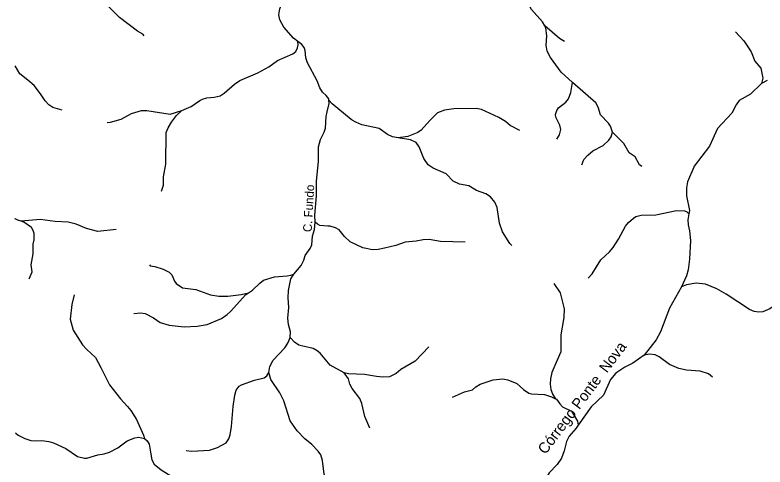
# Model space of a CAD drawing. Extents: x 473.9 to 500, y 7733.1 to 7760.8.
# Drawn here: x 473.92 to 480.86, y 7737.12 to 7741.31 of the extents above; entities that cross this region are included whole.
import ezdxf
from ezdxf.enums import TextEntityAlignment as Align

# ---------------------------------------------------------------- set-up
doc = ezdxf.new("R2010")
doc.units = 0
doc.header["$LTSCALE"] = 0.032
doc.layers.add('61', color=7, linetype='Continuous')
doc.layers.add('7', color=7, linetype='Continuous', lineweight=25)

msp = doc.modelspace()

# ---------------------------------------------------------------- linework, layer by layer
at = {"layer": '7'}
msp.add_line((480.8795, 7740.7), (480.8283, 7740.6712), dxfattribs=at)
for points in [[(476.5367, 7741.0622), (476.4959, 7741.093), (476.4064, 7741.1932), (476.3697, 7741.2629), (476.3611, 7741.3075), (476.3698, 7741.363), (476.4227, 7741.4977), (476.4668, 7741.6417), (476.4725, 7741.7305), (476.4574, 7741.8809), (476.4683, 7741.9924), (476.477, 7742.0153), (476.5332, 7742.0846), (476.7005, 7742.1941), (476.7489, 7742.2298), (476.7736, 7742.2599), (476.7997, 7742.3225), (476.7985, 7742.4024), (476.8151, 7742.4488), (476.8164, 7742.4524)], [(478.8237, 7741.2052), (478.8022, 7741.2433), (478.6995, 7741.3579), (478.6763, 7741.4023), (478.6692, 7741.427), (478.6711, 7741.5326), (478.639, 7741.658), (478.6382, 7741.6879), (478.6449, 7741.7268), (478.6824, 7741.8322), (478.6863, 7741.8993), (478.6996, 7741.9735), (478.7164, 7742.0043), (478.8564, 7742.1009), (478.9218, 7742.1576), (478.9456, 7742.1881)], [(475.1163, 7741.1132), (475.1013, 7741.1306), (475.0542, 7741.1583), (474.8855, 7741.2827), (474.793, 7741.3767), (474.6769, 7741.509), (474.6163, 7741.6049), (474.5903, 7741.6637), (474.578, 7741.7029), (474.5723, 7741.7783), (474.547, 7741.8325), (474.5162, 7741.882), (474.4613, 7741.9302), (474.4173, 7741.9689), (474.3764, 7742.0123), (474.3649, 7742.0365), (474.3658, 7742.0767), (474.3836, 7742.1527)], [(479.0794, 7740.6833), (478.9728, 7740.7761), (478.8759, 7740.9133), (478.8454, 7740.972), (478.8355, 7741.027), (478.8403, 7741.1121), (478.8308, 7741.1926), (478.8237, 7741.2052)], [(479.0038, 7741.0613), (478.9591, 7741.0894), (478.8237, 7741.2052)], [(480.5889, 7741.1508), (480.6655, 7741.0671), (480.7315, 7740.9659), (480.7673, 7740.8796), (480.8231, 7740.8132), (480.8414, 7740.7225), (480.8283, 7740.6712)], [(475.4648, 7740.4217), (475.5508, 7740.459), (475.6285, 7740.5147), (475.6555, 7740.5278), (475.6945, 7740.5398), (475.7625, 7740.5447), (475.8186, 7740.5585), (475.8565, 7740.5837), (475.9498, 7740.6673), (476.0009, 7740.7014), (476.1672, 7740.7712), (476.2676, 7740.8255), (476.3496, 7740.8857), (476.4921, 7740.9457), (476.5184, 7740.9699), (476.5345, 7741.0016), (476.5407, 7741.0314), (476.5367, 7741.0622)], [(476.8242, 7740.5167), (476.8231, 7740.5294), (476.7978, 7740.5626), (476.7639, 7740.5933), (476.7398, 7740.6315), (476.7145, 7740.6981), (476.6271, 7740.8632), (476.6105, 7740.9108), (476.6049, 7740.9778), (476.596, 7741.0073), (476.5743, 7741.0337), (476.5738, 7741.0343), (476.5367, 7741.0622)], [(474.356, 7740.4271), (474.2699, 7740.4506), (474.2331, 7740.4741), (474.1975, 7740.5118), (474.1551, 7740.5771), (474.0958, 7740.6532), (474.0395, 7740.7041), (473.9649, 7740.7616), (473.9194, 7740.8355)], [(478.9334, 7740.1578), (478.9575, 7740.1981), (478.9701, 7740.2462), (478.9627, 7740.286), (478.9242, 7740.362), (478.9228, 7740.3854), (478.9348, 7740.4234), (478.9506, 7740.4458), (479.0172, 7740.4995), (479.043, 7740.5319), (479.0623, 7740.5904), (479.0794, 7740.6833)], [(479.4502, 7740.2217), (479.4314, 7740.277), (479.4133, 7740.3056), (479.3366, 7740.3838), (479.3167, 7740.4534), (479.2956, 7740.4932), (479.0794, 7740.6833)], [(480.8283, 7740.6712), (480.7274, 7740.575), (480.6199, 7740.5164), (480.5921, 7740.4763), (480.5527, 7740.3963), (480.4199, 7740.255), (480.3463, 7740.0922), (480.2063, 7739.9073), (480.202, 7739.8973), (480.1446, 7739.7626), (480.1335, 7739.7078), (480.1351, 7739.6311), (480.1615, 7739.4974), (480.1565, 7739.4666)], [(476.6969, 7739.3887), (476.6939, 7739.4525), (476.7082, 7739.6311), (476.7099, 7739.7687), (476.7291, 7739.9515), (476.7276, 7740.0871), (476.7471, 7740.1553), (476.7804, 7740.2215), (476.7925, 7740.2603), (476.7997, 7740.3674), (476.8092, 7740.4093), (476.8269, 7740.4871), (476.8242, 7740.5167)], [(477.4664, 7740.168), (477.4128, 7740.1786), (477.3682, 7740.1988), (477.2895, 7740.256), (477.1293, 7740.2899), (477.0739, 7740.3137), (477.0394, 7740.3337), (477.032, 7740.338), (476.856, 7740.4832), (476.8242, 7740.5167)], [(474.7722, 7740.3117), (474.8045, 7740.314), (474.9021, 7740.3409), (474.9977, 7740.3939), (475.0887, 7740.4212), (475.14, 7740.4236), (475.3551, 7740.3891), (475.4648, 7740.4217)], [(475.2765, 7739.674), (475.293, 7739.7312), (475.2935, 7739.809), (475.3147, 7739.9249), (475.3184, 7740.2179), (475.3358, 7740.2605), (475.3673, 7740.3132), (475.413, 7740.375), (475.4648, 7740.4217)], [(478.5905, 7740.2379), (478.5028, 7740.283), (478.458, 7740.3203), (478.3982, 7740.358), (478.2365, 7740.4321), (478.1878, 7740.4413), (477.9812, 7740.4372), (477.8933, 7740.4252), (477.8308, 7740.3995), (477.7587, 7740.3314), (477.6798, 7740.2414), (477.6474, 7740.2185), (477.5536, 7740.1823), (477.4664, 7740.168)], [(479.165, 7739.9209), (479.184, 7739.9695), (479.2193, 7740.0083), (479.2681, 7740.0479), (479.3634, 7740.0974), (479.4165, 7740.1492), (479.4358, 7740.178), (479.4502, 7740.2217)], [(479.72, 7739.9041), (479.6989, 7739.9205), (479.6598, 7739.992), (479.604, 7740.0299), (479.555, 7740.1162), (479.4502, 7740.2217)], [(478.519, 7739.1731), (478.4978, 7739.1903), (478.4315, 7739.2993), (478.4048, 7739.3785), (478.3829, 7739.5251), (478.3595, 7739.5731), (478.3212, 7739.622), (478.2768, 7739.6505), (478.1913, 7739.6824), (478.1181, 7739.7251), (478.0333, 7739.7393), (477.9746, 7739.7667), (477.9101, 7739.8351), (477.7909, 7739.8887), (477.7444, 7739.9207), (477.7038, 7739.9768), (477.66, 7740.0868), (477.6314, 7740.1265), (477.5784, 7740.1512), (477.4664, 7740.168)], [(479.2247, 7738.8694), (479.2612, 7738.9101), (479.3408, 7739.0394), (479.42, 7739.1128), (479.4557, 7739.1538), (479.5051, 7739.2311), (479.5691, 7739.3524), (479.5958, 7739.3864), (479.6421, 7739.4268), (479.6642, 7739.4394), (479.7133, 7739.4542), (479.8502, 7739.4551), (480.042, 7739.4967), (480.1152, 7739.4945), (480.135, 7739.4863), (480.1565, 7739.4666)], [(473.9779, 7739.3974), (473.9451, 7739.4063), (473.9221, 7739.4206), (473.9215, 7739.4209)], [(474.8556, 7739.322), (474.6874, 7739.3028), (474.5809, 7739.3287), (474.4864, 7739.369), (474.4126, 7739.3884), (474.2897, 7739.3956), (474.1538, 7739.4117), (473.9779, 7739.3974)], [(480.1565, 7739.4666), (480.1472, 7739.4091), (480.1497, 7739.363), (480.1624, 7739.3072), (480.1704, 7739.2173), (480.1615, 7739.0464), (480.1495, 7738.9467), (480.1335, 7738.8909), (480.0869, 7738.7898)], [(474.0512, 7738.8626), (474.0768, 7738.9291), (474.0705, 7738.9942), (474.088, 7739.0939), (474.0872, 7739.1853), (474.0954, 7739.2258), (474.096, 7739.2821), (474.0879, 7739.311), (474.0708, 7739.3384), (474.0005, 7739.3885), (473.9779, 7739.3974)], [(476.5001, 7738.9084), (476.5687, 7738.9877), (476.5926, 7739.0375), (476.6042, 7739.0785), (476.6521, 7739.1432), (476.6666, 7739.1779), (476.673, 7739.2581), (476.6914, 7739.3219), (476.6969, 7739.3887)], [(478.0849, 7739.2048), (477.8562, 7739.2098), (477.752, 7739.229), (477.696, 7739.2249), (477.6324, 7739.2114), (477.5304, 7739.2024), (477.4429, 7739.1729), (477.3395, 7739.147), (477.28, 7739.1352), (477.2279, 7739.1328), (477.1383, 7739.1503), (477.022, 7739.2068), (476.9692, 7739.2558), (476.9192, 7739.3187), (476.8865, 7739.3371), (476.8349, 7739.3508), (476.8146, 7739.3526), (476.741, 7739.359), (476.719, 7739.3688), (476.6969, 7739.3887)], [(475.1648, 7738.9919), (475.1705, 7738.9854), (475.2148, 7738.9789), (475.2918, 7738.9518), (475.346, 7738.9266), (475.3698, 7738.901), (475.3948, 7738.8428), (475.4116, 7738.8195), (475.4698, 7738.7815), (475.5944, 7738.7646), (475.7294, 7738.7164), (475.8052, 7738.7038), (475.8897, 7738.7038), (476.012, 7738.7177), (476.0789, 7738.7332)], [(476.0789, 7738.7332), (476.1175, 7738.7574), (476.1845, 7738.8246), (476.2198, 7738.8499), (476.3211, 7738.8808), (476.4389, 7738.8911), (476.4735, 7738.8969), (476.5001, 7738.9084)], [(476.4651, 7738.3197), (476.4685, 7738.3742), (476.451, 7738.4413), (476.4436, 7738.5003), (476.4541, 7738.5984), (476.4477, 7738.6874), (476.4502, 7738.757), (476.4707, 7738.8627), (476.5001, 7738.9084)], [(478.9064, 7738.8203), (478.9652, 7738.7334), (479.0006, 7738.5874), (478.999, 7738.5045), (478.9718, 7738.3444), (478.9716, 7738.1876), (478.9169, 7738.0617), (478.8887, 7737.9969), (478.8739, 7737.9388), (478.8715, 7737.8888), (478.877, 7737.8386), (478.8923, 7737.7978), (478.8936, 7737.7943), (478.9224, 7737.753)], [(480.0869, 7738.7898), (479.9768, 7738.593), (479.8922, 7738.3727), (479.8524, 7738.2978), (479.7417, 7738.158)], [(481.2632, 7738.7589), (481.2329, 7738.7623), (481.1758, 7738.7543), (481.0986, 7738.7269), (481.0411, 7738.6965), (480.9495, 7738.6162), (480.9062, 7738.5858), (480.8401, 7738.5582), (480.8046, 7738.5547), (480.7593, 7738.5622), (480.7158, 7738.581), (480.5023, 7738.7214), (480.4141, 7738.7696), (480.309, 7738.8145), (480.2236, 7738.8249), (480.1332, 7738.8067), (480.0869, 7738.7898)], [(474.4667, 7738.7164), (474.4456, 7738.6257), (474.4313, 7738.4902), (474.4567, 7738.389), (474.5436, 7738.2524), (474.5828, 7738.2082), (474.6633, 7738.1343), (474.7147, 7738.043), (474.7932, 7737.8825), (474.896, 7737.7523), (474.9598, 7737.6803), (474.9905, 7737.6457), (475.0436, 7737.5599), (475.1094, 7737.4156), (475.1175, 7737.3864)], [(475.0202, 7738.544), (475.0831, 7738.5491), (475.1234, 7738.5412), (475.2025, 7738.5033), (475.2619, 7738.4596), (475.3461, 7738.4334), (475.4857, 7738.4207), (475.6053, 7738.4248), (475.6978, 7738.44), (475.8292, 7738.4975), (475.8822, 7738.5338), (475.9143, 7738.5609), (476.057, 7738.7195), (476.0789, 7738.7332)], [(476.2697, 7737.9963), (476.2785, 7738.0516), (476.3083, 7738.1099), (476.4156, 7738.2249), (476.4276, 7738.2425), (476.4487, 7738.2735), (476.4651, 7738.3197)], [(476.967, 7737.9938), (476.8355, 7738.0635), (476.7441, 7738.1765), (476.7174, 7738.1984), (476.679, 7738.2184), (476.5701, 7738.2446), (476.545, 7738.2506), (476.5058, 7738.2781), (476.4651, 7738.3197)], [(477.748, 7738.2333), (477.6237, 7738.1007), (477.4909, 7738.0246), (477.4465, 7737.9861), (477.3865, 7737.9566), (477.3218, 7737.9534), (477.2663, 7737.9582), (477.1543, 7737.9765), (477.0062, 7737.9838), (476.967, 7737.9938)], [(480.3746, 7737.9539), (480.3382, 7737.9847), (480.2614, 7738.0087), (480.1328, 7738.0183), (480.062, 7738.0325), (479.9774, 7738.0694), (479.8823, 7738.1413), (479.8426, 7738.1595), (479.7908, 7738.1667), (479.7417, 7738.158)], [(479.7417, 7738.158), (479.6374, 7738.0829), (479.5632, 7738.0458), (479.4811, 7737.9914), (479.4306, 7737.9304), (479.3655, 7737.786), (479.2513, 7737.6787), (479.1304, 7737.5072)], [(475.5024, 7737.274), (475.5551, 7737.2686), (475.7194, 7737.2783), (475.7926, 7737.3022), (475.873, 7737.3457), (475.8982, 7737.3819), (475.9113, 7737.4185), (475.9233, 7737.4956), (475.9389, 7737.6802), (475.9539, 7737.7876), (475.9676, 7737.8324), (475.993, 7737.8683), (476.0142, 7737.8837), (476.1358, 7737.9268), (476.2242, 7737.9462), (476.251, 7737.9668), (476.2697, 7737.9963)], [(477.0495, 7736.5475), (476.9609, 7736.6233), (476.9045, 7736.7197), (476.8729, 7736.8359), (476.7804, 7737.0548), (476.7661, 7737.1823), (476.7491, 7737.2341), (476.7253, 7737.2692), (476.6653, 7737.3299), (476.6007, 7737.3834), (476.5315, 7737.4575), (476.467, 7737.5501), (476.4067, 7737.7331), (476.3689, 7737.8078), (476.2859, 7737.933), (476.2697, 7737.9963)], [(477.2038, 7737.4806), (477.1578, 7737.5891), (477.1288, 7737.7102), (477.111, 7737.7562), (477.0393, 7737.8474), (477.0192, 7737.8886), (477.0061, 7737.9374), (476.967, 7737.9938)], [(477.9694, 7737.7678), (478.0801, 7737.817), (478.1548, 7737.8348), (478.1843, 7737.8627), (478.2258, 7737.887), (478.3458, 7737.9277), (478.434, 7737.9364), (478.4815, 7737.9277), (478.5644, 7737.8931), (478.6256, 7737.8384), (478.6752, 7737.8052), (478.6993, 7737.7989), (478.8198, 7737.793), (478.8766, 7737.7752), (478.8834, 7737.7719), (478.9224, 7737.753)], [(478.9224, 7737.753), (478.9318, 7737.7484), (478.9602, 7737.7058), (478.986, 7737.6798), (479.07, 7737.6385), (479.1248, 7737.5448), (479.1304, 7737.5072)], [(479.1304, 7737.5072), (479.1134, 7737.4801), (479.0472, 7737.406), (479.0245, 7737.3573), (479.0023, 7737.2715), (479.0022, 7737.2713), (478.9762, 7737.203), (478.938, 7737.1459), (478.8628, 7737.0668), (478.7764, 7736.9225), (478.7165, 7736.8575), (478.7077, 7736.8415)], [(473.9246, 7737.4378), (473.9273, 7737.4352), (473.9488, 7737.4152), (474.0101, 7737.3846), (474.0649, 7737.3674), (474.1102, 7737.3625), (474.1692, 7737.3656), (474.2336, 7737.3577), (474.2747, 7737.3461), (474.3895, 7737.2934), (474.497, 7737.2172), (474.5616, 7737.2029), (474.584, 7737.2035), (474.6868, 7737.2327), (474.7441, 7737.2426), (474.793, 7737.2595), (474.8709, 7737.2992), (474.958, 7737.3624), (475.029, 7737.3903), (475.0634, 7737.3968), (475.1175, 7737.3864)], [(475.1175, 7737.3864), (475.143, 7737.3643), (475.1598, 7737.3342), (475.1727, 7737.2579), (475.1844, 7737.1887), (475.2078, 7737.1481), (475.2713, 7737.0952), (475.4901, 7736.9601), (475.6424, 7736.7907)]]:
    msp.add_lwpolyline(points, dxfattribs=at)

# ---------------------------------------------------------------- texts
at = {"layer": '61'}
for s, height, rotation, p in [('C. Fundo', 0.08, 86.806, (476.6769, 7739.5143)), ('Córrego Ponte  Nova', 0.1, 52.995, (479.2071, 7737.733))]:
    msp.add_text(s, height=height, rotation=rotation, dxfattribs=at).set_placement(p, align=Align.CENTER)

doc.saveas('drawing.dxf')
